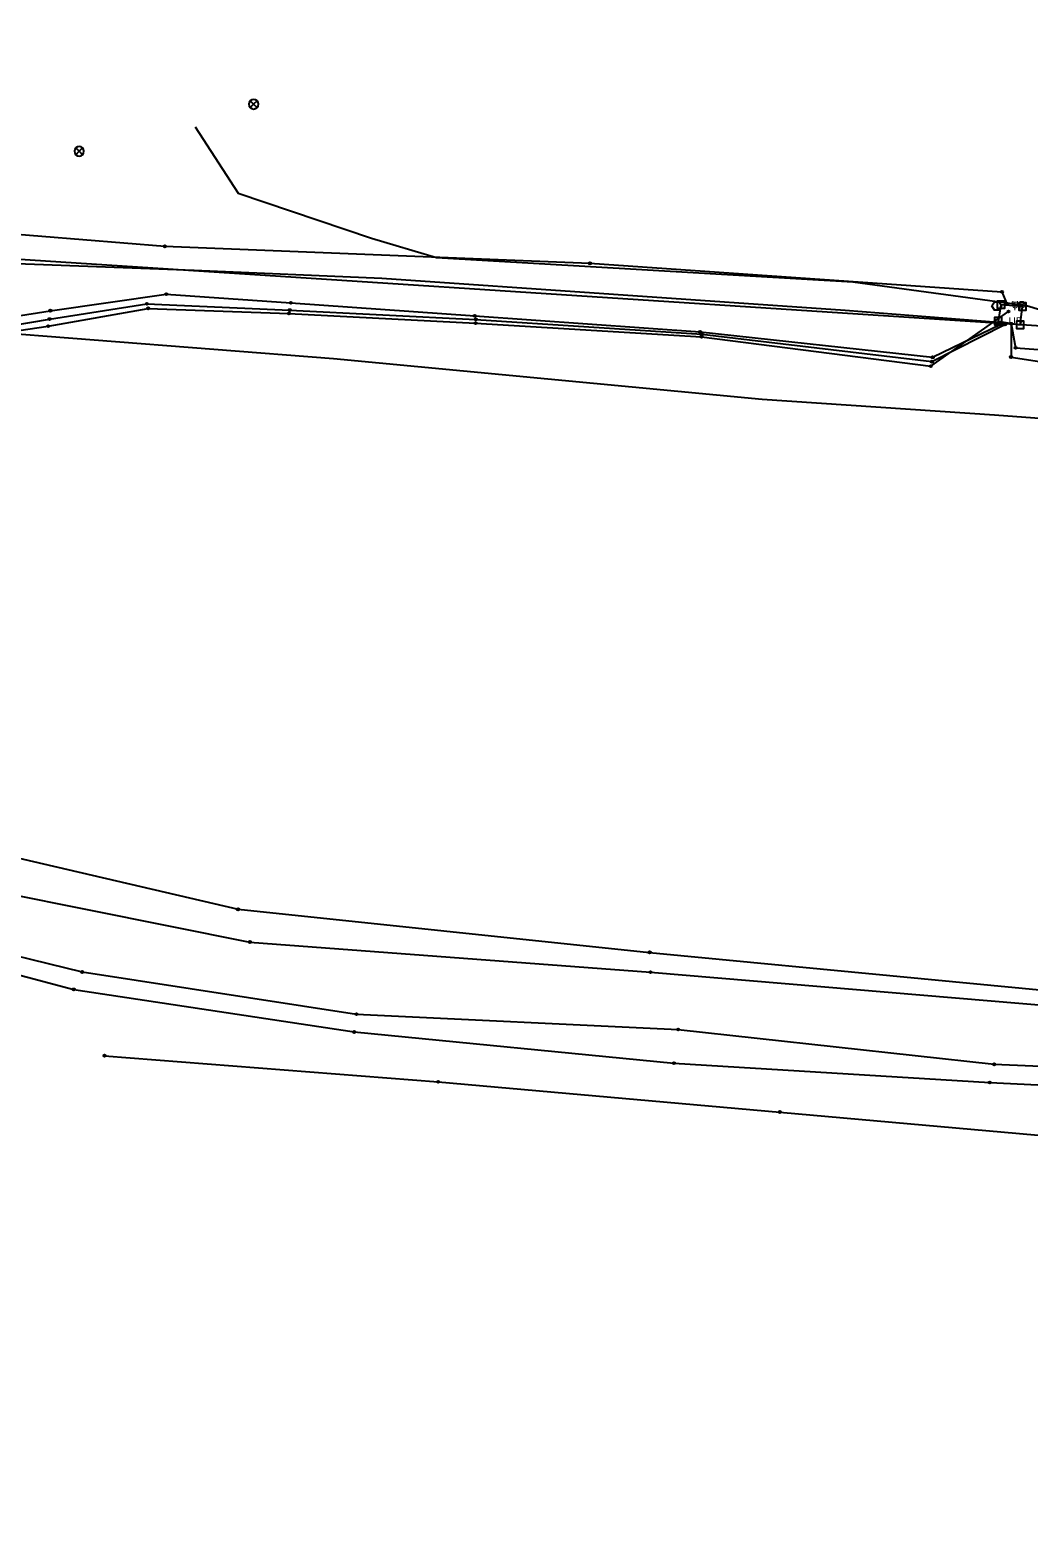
# Model space of a CAD drawing. Extents: x 20500343 to 20505311, y 7953484 to 7954193.
# Drawn here: x 20502739.5 to 20502927.2, y 7953635.3 to 7953918.7 of the extents above; entities that cross this region are included whole.
import ezdxf

# ---------------------------------------------------------------- set-up
doc = ezdxf.new("R2010")
doc.units = 0
for name, color, linetype in [('C-PROP-LINE-LOT', 7, 'Continuous'), ('V-ANNO-NOTE', 7, 'Continuous'), ('V-MON-FND', 7, 'Continuous'), ('V-SITE-FENC', 7, 'Continuous'), ('V-SSWR-STRC', 7, 'Continuous')]:
    doc.layers.add(name, color=color, linetype=linetype)

msp = doc.modelspace()

# ---------------------------------------------------------------- linework, layer by layer
at = {"layer": 'C-PROP-LINE-LOT'}
for points in [[(20502603.44, 7953918.66), (20502605.26, 7953902.99), (20502609.92, 7953888.17), (20502622.1, 7953882.7), (20502640.25, 7953884.52), (20502671.71, 7953886.63), (20502718.58, 7953881.8), (20502764.86, 7953878.03), (20502844.74, 7953874.85), (20502922.16, 7953869.49), (20502923.06, 7953867.25)], [(20502770.58, 7953900.5), (20502778.64, 7953888), (20502803.68, 7953879.58), (20502815.92, 7953875.93), (20502894.16, 7953871.34), (20502926.75, 7953866.94), (20502942.15, 7953862.29), (20502942.54, 7953863.75)], [(20502692.45, 7953878.59), (20502942.15, 7953862.29), (20503185.94, 7953841.4)], [(20502694.42, 7953878.2), (20502726.94, 7953875.21), (20502770.34, 7953873.56), (20502805.65, 7953872.03), (20502892.71, 7953866.01), (20502921.42, 7953863.8)], [(20502619.3, 7953874.37), (20502654.48, 7953870.28), (20502729.02, 7953862.23), (20502796.55, 7953856.97), (20502877.1, 7953849.29), (20502920.79, 7953846.35), (20502948.65, 7953844.32)], [(20502604.3, 7953858.98), (20502629.37, 7953859.07), (20502656.51, 7953859.31), (20502681.15, 7953859.64), (20502705.7, 7953860.48), (20502725.32, 7953863.09), (20502743.33, 7953865.93), (20502765.13, 7953869.05), (20502788.54, 7953867.4), (20502823.08, 7953864.96), (20502865.42, 7953861.97), (20502909.13, 7953857.18), (20502921.96, 7953863.39)], [(20502604.63, 7953857.57), (20502629.33, 7953858.26), (20502655.96, 7953858.62), (20502681.16, 7953859.09), (20502705.87, 7953859.77), (20502725.04, 7953861.28), (20502743.18, 7953864.36), (20502761.47, 7953867.22), (20502788.32, 7953866.05), (20502823.3, 7953864.3), (20502865.74, 7953861.5), (20502909, 7953856.36), (20502922.72, 7953863.34)], [(20502604.8, 7953856.97), (20502629.91, 7953857.63), (20502655.82, 7953858.13), (20502681.23, 7953858.7), (20502705.86, 7953859.16), (20502725.06, 7953860.42), (20502742.94, 7953863.02), (20502761.73, 7953866.37), (20502788.18, 7953865.42), (20502823.26, 7953863.59), (20502865.72, 7953861.02), (20502908.79, 7953855.5), (20502923.38, 7953865.78)], [(20502923.89, 7953863.48), (20502923.87, 7953857.22), (20502949.69, 7953853.27), (20502980.21, 7953850.33), (20503012.7, 7953848.26), (20503049, 7953845.63), (20503082.17, 7953842.1), (20503112.95, 7953839.56), (20503138.35, 7953837.73), (20503193.47, 7953832.98), (20503218.34, 7953830.79), (20503248.23, 7953827.27), (20503280.04, 7953825.39), (20503302.66, 7953821.04), (20503373.35, 7953815.08), (20503420.82, 7953809.31), (20503465.76, 7953808.12), (20503523.4, 7953802.43), (20503558.95, 7953800.72), (20503614.46, 7953794.57), (20503665.44, 7953787.94), (20503677.02, 7953787.65), (20503693.06, 7953785.61)], [(20502923.89, 7953863.47), (20502924.73, 7953858.96), (20502949.8, 7953857.13), (20502979.15, 7953855.66), (20503010.57, 7953853.39), (20503049.45, 7953848.56), (20503082.45, 7953846.12), (20503112.47, 7953843.06), (20503138.8, 7953840.76), (20503301.69, 7953823.49), (20503373.91, 7953818.29), (20503420.2, 7953815.98), (20503466.21, 7953810.37), (20503524.2, 7953805.14), (20503558.57, 7953802.46), (20503613.81, 7953798.05), (20503665.73, 7953789.96), (20503676.95, 7953790.93), (20503697.66, 7953791.85), (20503755.76, 7953785.45), (20503787.39, 7953784.49)], [(20502585.16, 7953780.62), (20502703.53, 7953770.96), (20502778.6, 7953753.43), (20502855.95, 7953745.33), (20502958.04, 7953735.55), (20503064.82, 7953724.97), (20503167.9, 7953714.97), (20503186.63, 7953713.33), (20503187.62, 7953709.92)], [(20502583.99, 7953772.95), (20502610.65, 7953768.87), (20502654.81, 7953765.56), (20502704, 7953762.66), (20502780.84, 7953747.28), (20502856.1, 7953741.6), (20502958.12, 7953733.02), (20503064.96, 7953721.73), (20503167.51, 7953711.49), (20503200.31, 7953708.91), (20503261.33, 7953704.35), (20503308.48, 7953700.62), (20503425.37, 7953689.03), (20503525.59, 7953683.92), (20503632.36, 7953675.44)], [(20502567.82, 7953767.29), (20502613.16, 7953765.86), (20502660.75, 7953761.57), (20502684.96, 7953758.32), (20502704.25, 7953752.73), (20502749.31, 7953741.65), (20502800.87, 7953733.72), (20502861.3, 7953730.84), (20502920.69, 7953724.3), (20502983.15, 7953721.6), (20503039.18, 7953715.3), (20503094.87, 7953710.44), (20503155.33, 7953704.72), (20503201.09, 7953699.55), (20503255.71, 7953694.61), (20503304.33, 7953690.28), (20503344.16, 7953687.19), (20503374.46, 7953685.7), (20503426.83, 7953682.97), (20503524.49, 7953672.95), (20503631.72, 7953664.81)], [(20502567.9, 7953761.34), (20502613.51, 7953762.6), (20502660.72, 7953759.56), (20502684.44, 7953756.31), (20502703.23, 7953750.18), (20502747.73, 7953738.37), (20502800.44, 7953730.37), (20502860.52, 7953724.51), (20502919.86, 7953720.87), (20502983.04, 7953717.79), (20503038.66, 7953709.78), (20503094.29, 7953705.56), (20503153.13, 7953700.69), (20503201.01, 7953696.62), (20503255.42, 7953690.81), (20503303.52, 7953686.48), (20503344.16, 7953683.02), (20503374.14, 7953680.96), (20503426.87, 7953677.14), (20503523.93, 7953669.23), (20503630.84, 7953663.08)], [(20502753.52, 7953725.91), (20502816.21, 7953720.99), (20502880.43, 7953715.32), (20503003.58, 7953704.35), (20503122.54, 7953695.27), (20503239.48, 7953685.69), (20503360, 7953675.01), (20503474.19, 7953666.22), (20503697.41, 7953647.35), (20503810.09, 7953637.77), (20503838.81, 7953635.29)]]:
    msp.add_lwpolyline(points, dxfattribs=at)
at = {"layer": 'V-ANNO-NOTE'}
for centre in [(20502764.86, 7953878.03), (20502844.74, 7953874.85), (20502765.13, 7953869.05), (20502922.16, 7953869.49), (20502743.33, 7953865.93), (20502761.47, 7953867.22), (20502761.73, 7953866.37), (20502788.18, 7953865.42), (20502788.32, 7953866.05), (20502788.54, 7953867.4), (20502923.06, 7953867.25), (20502923.38, 7953865.78), (20502742.94, 7953863.02), (20502743.18, 7953864.36), (20502823.08, 7953864.96), (20502823.26, 7953863.59), (20502823.3, 7953864.3), (20502921.96, 7953863.39), (20502922.72, 7953863.34), (20502923.89, 7953863.48), (20502923.89, 7953863.47), (20502865.42, 7953861.97), (20502865.72, 7953861.02), (20502865.74, 7953861.5), (20502909.13, 7953857.18), (20502923.87, 7953857.22), (20502924.73, 7953858.96), (20502908.79, 7953855.5), (20502909, 7953856.36), (20502778.6, 7953753.43), (20502780.84, 7953747.28), (20502855.95, 7953745.33), (20502749.31, 7953741.65), (20502856.1, 7953741.6), (20502747.73, 7953738.37), (20502800.87, 7953733.72), (20502800.44, 7953730.37), (20502861.3, 7953730.84), (20502753.52, 7953725.91), (20502860.52, 7953724.51), (20502920.69, 7953724.3), (20502816.21, 7953720.99), (20502919.86, 7953720.87), (20502880.43, 7953715.32)]:
    msp.add_circle(centre, 0.2, dxfattribs=at)
at = {"layer": 'V-MON-FND'}
msp.add_lwpolyline([(20502920.28, 7953866.83), (20502920.73, 7953867.62), (20502921.65, 7953867.62), (20502922.1, 7953866.83), (20502921.65, 7953866.04), (20502920.73, 7953866.04), (20502920.28, 7953866.83)], dxfattribs=at)
msp.add_lwpolyline([(20502921.98, 7953867.06), (20502921.42, 7953863.97), (20502925.6, 7953863.29), (20502926, 7953866.73)], close=True, dxfattribs=at)
msp.add_lwpolyline([(20502921.98, 7953867.06), (20502921.42, 7953863.97), (20502925.6, 7953863.29), (20502926, 7953866.73)], close=True, dxfattribs=at)
at = {"layer": 'V-SITE-FENC'}
for points in [[(20502921.98, 7953866.38), (20502921.98, 7953866.38), (20502922.67, 7953866.38), (20502922.67, 7953867.75), (20502921.29, 7953867.75), (20502921.29, 7953866.38), (20502921.98, 7953866.38)], [(20502926, 7953866.05), (20502926, 7953866.05), (20502926.69, 7953866.05), (20502926.69, 7953867.42), (20502925.31, 7953867.42), (20502925.31, 7953866.05), (20502926, 7953866.05)], [(20502921.42, 7953863.28), (20502921.42, 7953863.28), (20502922.11, 7953863.28), (20502922.11, 7953864.65), (20502920.73, 7953864.65), (20502920.73, 7953863.28), (20502921.42, 7953863.28)], [(20502925.6, 7953862.6), (20502925.6, 7953862.6), (20502926.29, 7953862.6), (20502926.29, 7953863.97), (20502924.91, 7953863.97), (20502924.91, 7953862.6), (20502925.6, 7953862.6)]]:
    msp.add_lwpolyline(points, dxfattribs=at)
at = {"layer": 'V-SSWR-STRC'}
for points in [[(20502780.9, 7953904.11), (20502781.54, 7953904.74), (20502780.9, 7953905.38)], [(20502782.18, 7953905.38), (20502781.54, 7953904.74), (20502782.18, 7953904.11)], [(20502748.12, 7953895.25), (20502748.76, 7953895.89), (20502748.12, 7953896.52)], [(20502749.4, 7953896.52), (20502748.76, 7953895.89), (20502749.4, 7953895.25)]]:
    msp.add_lwpolyline(points, dxfattribs=at)
for centre, start, end in [((20502781.54, 7953904.74), 135, 225), ((20502781.54, 7953904.74), 45, 135), ((20502781.54, 7953904.74), 315, 45), ((20502781.54, 7953904.74), 225, 315), ((20502748.76, 7953895.89), 45, 135), ((20502748.76, 7953895.89), 135, 225), ((20502748.76, 7953895.89), 225, 315), ((20502748.76, 7953895.89), 315, 45)]:
    msp.add_arc(centre, 0.899, start, end, dxfattribs=at)

# ---------------------------------------------------------------- texts
at = {"layer": 'V-MON-FND'}
msp.add_text('TP', height=1.599, dxfattribs=at).set_placement((20502923.93, 7953866.03))
at = {"layer": 'V-SITE-FENC'}
for p in [(20502923.97, 7953866.38), (20502923.41, 7953863.29)]:
    msp.add_text('UB', height=1.399, dxfattribs=at).set_placement(p)

doc.saveas('drawing.dxf')
